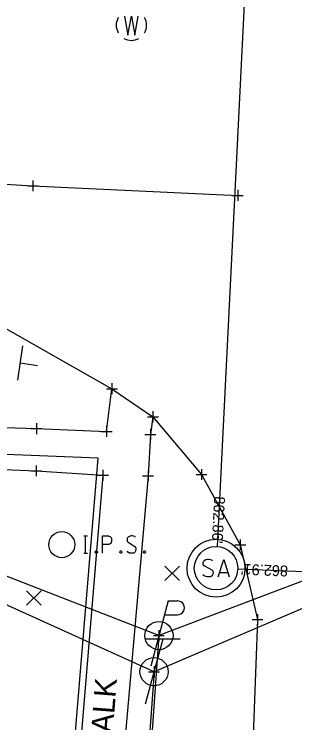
# Model space of a CAD drawing. Extents: x 1380550 to 1381945, y 468927 to 470496.
# Drawn here: x 1381582.5 to 1381608.3, y 470212.8 to 470278.1 of the extents above; entities that cross this region are included whole.
import ezdxf

# ---------------------------------------------------------------- set-up
doc = ezdxf.new("R2010")
doc.units = 0
for name, color, linetype in [('DR_X_Storm_Sewer', 7, 'Continuous'), ('DR_X_Text', 7, 'Continuous'), ('GK_Drainage_Nodes', 7, 'Continuous'), ('PV_X_COP', 7, 'Continuous'), ('PV_X_EOP', 7, 'Continuous'), ('PV_X_Walk', 7, 'Continuous'), ('RD_X_Text', 7, 'Continuous'), ('RW_X_Esmt_General', 7, 'Continuous'), ('SC_Scratch1', 7, 'Continuous'), ('SN_X_Public', 7, 'Continuous'), ('SV_P_Mon_Cells_Set', 7, 'Continuous'), ('SV_X_Random_Point', 7, 'Continuous'), ('SV_X_Shot_Marker', 7, 'Continuous'), ('UT_X_Electric', 7, 'Continuous'), ('UT_X_Electric_Cells', 7, 'Continuous'), ('UT_X_Sanitary_Cells', 7, 'Continuous'), ('UT_X_Sanitary_Line', 7, 'Continuous'), ('UT_X_Telecom', 7, 'Continuous'), ('UT_X_Telecom_Cells', 7, 'Continuous'), ('UT_X_Water_Cells', 7, 'Continuous')]:
    doc.layers.add(name, color=color, linetype=linetype)

msp = doc.modelspace()

# ---------------------------------------------------------------- linework, layer by layer
at = {"layer": 'DR_X_Storm_Sewer'}
msp.add_line((1381906.161, 470214.727), (1381603.055, 470226.96), dxfattribs=at)
at = {"layer": 'GK_Drainage_Nodes'}
for p, q in [((1381601.057, 470229.041), (1381601.057, 470229.041)), ((1381601.057, 470227.041), (1381601.057, 470227.041)), ((1381601.057, 470227.041), (1381601.057, 470227.041)), ((1381601.057, 470227.041), (1381601.057, 470227.041)), ((1381601.057, 470225.041), (1381601.057, 470225.041))]:
    msp.add_line(p, q, dxfattribs=at)
msp.add_circle((1381601.057, 470227.041), 2, dxfattribs=at)
at = {"layer": 'PV_X_COP'}
msp.add_lwpolyline([(1381547.543, 470264.484), (1381567.85, 470263.258), (1381584.182, 470262.283), (1381603.07, 470261.395)], dxfattribs=at)
at = {"layer": 'PV_X_EOP'}
msp.add_lwpolyline([(1381575.388, 470244.04), (1381576.993, 470244.172), (1381579.545, 470245.54), (1381580.634, 470247.96), (1381580.965, 470249.541), (1381591.472, 470243.585), (1381595.246, 470241.001), (1381599.724, 470235.672), (1381603.295, 470229.192), (1381604.877, 470222.306), (1381604.1, 470201.731), (1381602.36, 470179.429), (1381598.627, 470125.511), (1381593.594, 470071.886), (1381589.534, 470020.646), (1381585.494, 469971.089), (1381582.039, 469928.84), (1381578.382, 469880.278), (1381576.859, 469862.024), (1381576.832, 469860.709), (1381576.155, 469857.385), (1381571.588, 469847.123), (1381563.138, 469838.251)], dxfattribs=at)
at = {"layer": 'PV_X_Walk'}
for points in [[(1381542.819, 470241.667), (1381568.313, 470240.569), (1381578.584, 470240.095), (1381584.519, 470239.902), (1381590.984, 470239.649), (1381591.472, 470243.585)], [(1381595.246, 470241.001), (1381595.008, 470239.378), (1381594.794, 470235.558), (1381591.944, 470203.127), (1381590.146, 470180.146), (1381585.845, 470126.107), (1381581.453, 470072.835), (1381577.219, 470021.474), (1381573.16, 469971.68), (1381569.701, 469929.431), (1381565.599, 469880.892), (1381564.412, 469866.997), (1381562.952, 469848.389), (1381561.899, 469840.883)], [(1381542.564, 470237.64), (1381568.337, 470236.695), (1381578.506, 470236.262), (1381584.487, 470236.02), (1381590.642, 470235.62), (1381587.955, 470203.415), (1381586.625, 470180.461), (1381581.932, 470126.464), (1381577.652, 470073.239), (1381573.197, 470021.541), (1381569.148, 469971.738), (1381565.643, 469929.65), (1381561.644, 469881.156), (1381560.457, 469867.318), (1381559.272, 469848.708), (1381558.347, 469840.136)]]:
    msp.add_lwpolyline(points, dxfattribs=at)
at = {"layer": 'RW_X_Esmt_General'}
msp.add_lwpolyline([(1381490.401, 469029.464), (1381590.199, 470237.184), (1380558.689, 470277.035)], dxfattribs=at)
at = {"layer": 'SN_X_Public'}
for p, q in [((1381582.814, 470244.371), (1381583.252, 470247.541)), ((1381583.033, 470245.956), (1381584.618, 470245.737))]:
    msp.add_line(p, q, dxfattribs=at)
at = {"layer": 'SV_P_Mon_Cells_Set'}
for points in [[(1381588.87, 470230.016), (1381589.223, 470230.016)], [(1381589.046, 470228.416), (1381589.046, 470230.016)], [(1381590.612, 470228.416), (1381590.612, 470230.016), (1381591.141, 470230.016), (1381591.196, 470230.003), (1381591.273, 470229.978), (1381591.306, 470229.953), (1381591.339, 470229.928), (1381591.383, 470229.865), (1381591.416, 470229.802), (1381591.438, 470229.701), (1381591.438, 470229.55), (1381591.427, 470229.499), (1381591.405, 470229.424), (1381591.361, 470229.336), (1381591.317, 470229.298), (1381591.284, 470229.273), (1381591.229, 470229.247), (1381591.141, 470229.235), (1381590.612, 470229.235)], [(1381593.621, 470229.902), (1381593.599, 470229.928), (1381593.566, 470229.953), (1381593.467, 470229.991), (1381593.345, 470230.016), (1381593.257, 470230.016), (1381593.224, 470230.016), (1381593.081, 470229.978), (1381592.96, 470229.902), (1381592.882, 470229.802), (1381592.86, 470229.701), (1381592.86, 470229.625), (1381592.882, 470229.524), (1381592.971, 470229.436), (1381593.577, 470229.058), (1381593.632, 470229.008), (1381593.654, 470228.958), (1381593.676, 470228.882), (1381593.676, 470228.806), (1381593.665, 470228.731), (1381593.654, 470228.681), (1381593.632, 470228.617), (1381593.61, 470228.567), (1381593.588, 470228.529), (1381593.555, 470228.491), (1381593.522, 470228.466), (1381593.478, 470228.441), (1381593.445, 470228.429), (1381593.345, 470228.416), (1381593.191, 470228.416), (1381593.092, 470228.441), (1381592.948, 470228.529), (1381592.86, 470228.605)], [(1381590.005, 470228.63), (1381590.06, 470228.63), (1381590.094, 470228.605), (1381590.127, 470228.555), (1381590.127, 470228.491), (1381590.094, 470228.441), (1381590.06, 470228.416), (1381590.005, 470228.416), (1381589.972, 470228.441), (1381589.939, 470228.491), (1381589.939, 470228.555), (1381589.972, 470228.605), (1381590.005, 470228.63)], [(1381592.254, 470228.63), (1381592.309, 470228.63), (1381592.342, 470228.605), (1381592.375, 470228.555), (1381592.375, 470228.491), (1381592.342, 470228.441), (1381592.309, 470228.416), (1381592.254, 470228.416), (1381592.221, 470228.441), (1381592.188, 470228.491), (1381592.188, 470228.555), (1381592.221, 470228.605), (1381592.254, 470228.63)], [(1381594.437, 470228.63), (1381594.492, 470228.63), (1381594.525, 470228.605), (1381594.558, 470228.555), (1381594.558, 470228.491), (1381594.525, 470228.441), (1381594.492, 470228.416), (1381594.437, 470228.416), (1381594.403, 470228.441), (1381594.371, 470228.491), (1381594.371, 470228.555), (1381594.403, 470228.605), (1381594.437, 470228.63)], [(1381588.87, 470228.416), (1381589.223, 470228.416)]]:
    msp.add_lwpolyline(points, dxfattribs=at)
msp.add_circle((1381586.851, 470229.214), 1.2, dxfattribs=at)
at = {"layer": 'SV_X_Random_Point'}
for p, q in [((1381596.356, 470225.899), (1381597.69, 470227.234)), ((1381596.356, 470227.234), (1381597.69, 470225.899)), ((1381583.61, 470223.635), (1381584.944, 470224.97)), ((1381583.61, 470224.97), (1381584.944, 470223.635))]:
    msp.add_line(p, q, dxfattribs=at)
at = {"layer": 'SV_X_Shot_Marker'}
for p, q in [((1381584.182, 470262.783), (1381584.182, 470261.783)), ((1381583.682, 470262.283), (1381584.682, 470262.283)), ((1381584.182, 470262.283), (1381584.182, 470262.283)), ((1381603.07, 470261.895), (1381603.07, 470260.895)), ((1381602.57, 470261.395), (1381603.57, 470261.395)), ((1381603.07, 470261.395), (1381603.07, 470261.395)), ((1381590.972, 470243.585), (1381591.972, 470243.585)), ((1381590.972, 470243.585), (1381591.972, 470243.585)), ((1381591.472, 470244.085), (1381591.472, 470243.085)), ((1381591.472, 470244.085), (1381591.472, 470243.085)), ((1381591.472, 470243.585), (1381591.472, 470243.585)), ((1381591.472, 470243.585), (1381591.472, 470243.585)), ((1381594.746, 470241.001), (1381595.746, 470241.001)), ((1381594.746, 470241.001), (1381595.746, 470241.001)), ((1381594.746, 470241.001), (1381595.746, 470241.001)), ((1381595.246, 470241.501), (1381595.246, 470240.501)), ((1381595.246, 470241.501), (1381595.246, 470240.501)), ((1381595.246, 470241.501), (1381595.246, 470240.501)), ((1381595.246, 470241.001), (1381595.246, 470241.001)), ((1381595.246, 470241.001), (1381595.246, 470241.001)), ((1381595.246, 470241.001), (1381595.246, 470241.001)), ((1381584.519, 470240.402), (1381584.519, 470239.402)), ((1381584.019, 470239.902), (1381585.019, 470239.902)), ((1381584.519, 470239.902), (1381584.519, 470239.902)), ((1381590.484, 470239.649), (1381591.484, 470239.649)), ((1381590.984, 470240.149), (1381590.984, 470239.149)), ((1381590.984, 470239.649), (1381590.984, 470239.649)), ((1381595.008, 470239.878), (1381595.008, 470238.878)), ((1381594.508, 470239.378), (1381595.508, 470239.378)), ((1381595.008, 470239.378), (1381595.008, 470239.378)), ((1381584.487, 470236.52), (1381584.487, 470235.52)), ((1381583.987, 470236.02), (1381584.987, 470236.02)), ((1381584.487, 470236.02), (1381584.487, 470236.02)), ((1381590.642, 470236.12), (1381590.642, 470235.12)), ((1381594.794, 470236.058), (1381594.794, 470235.058)), ((1381599.224, 470235.672), (1381600.224, 470235.672)), ((1381599.724, 470236.172), (1381599.724, 470235.172)), ((1381599.724, 470235.672), (1381599.724, 470235.672)), ((1381590.142, 470235.62), (1381591.142, 470235.62)), ((1381590.642, 470235.62), (1381590.642, 470235.62)), ((1381594.294, 470235.558), (1381595.294, 470235.558)), ((1381594.794, 470235.558), (1381594.794, 470235.558)), ((1381602.795, 470229.192), (1381603.795, 470229.192)), ((1381603.295, 470229.692), (1381603.295, 470228.692)), ((1381603.295, 470229.192), (1381603.295, 470229.192)), ((1381604.877, 470222.806), (1381604.877, 470221.806)), ((1381604.377, 470222.306), (1381605.377, 470222.306)), ((1381604.877, 470222.306), (1381604.877, 470222.306)), ((1381595.795, 470221.333), (1381595.795, 470220.333)), ((1381595.795, 470221.333), (1381595.795, 470220.333)), ((1381595.295, 470220.833), (1381596.295, 470220.833)), ((1381595.295, 470220.833), (1381596.295, 470220.833)), ((1381595.795, 470220.833), (1381595.795, 470220.833)), ((1381595.795, 470220.833), (1381595.795, 470220.833)), ((1381595.346, 470218.01), (1381595.346, 470217.01)), ((1381595.346, 470218.01), (1381595.346, 470217.01)), ((1381594.846, 470217.51), (1381595.846, 470217.51)), ((1381594.846, 470217.51), (1381595.846, 470217.51)), ((1381595.346, 470217.51), (1381595.346, 470217.51)), ((1381595.346, 470217.51), (1381595.346, 470217.51))]:
    msp.add_line(p, q, dxfattribs=at)
at = {"layer": 'UT_X_Electric'}
for points in [[(1381665.562, 470247.404), (1381595.795, 470220.833), (1381581.264, 470018.199), (1381571.968, 469887.64), (1381559.775, 469757.408), (1381543.86, 469565.781), (1381529.165, 469390.12), (1381515.279, 469203.101), (1381540.8, 469054.263)], [(1381595.795, 470220.833), (1381540.532, 470242.354)]]:
    msp.add_lwpolyline(points, dxfattribs=at)
at = {"layer": 'UT_X_Electric_Cells'}
for p, q in [((1381596.652, 470224.033), (1381595.045, 470218.033)), ((1381596.652, 470224.033), (1381597.502, 470224.033)), ((1381596.31, 470222.758), (1381597.502, 470222.758))]:
    msp.add_line(p, q, dxfattribs=at)
msp.add_circle((1381595.795, 470220.833), 1.3, dxfattribs=at)
msp.add_arc((1381597.514, 470223.396), 0.638, 268.8767, 91.1233, dxfattribs=at)
at = {"layer": 'UT_X_Sanitary_Cells'}
for points in [[(1381600.724, 470227.727), (1381600.699, 470227.753), (1381600.661, 470227.778), (1381600.548, 470227.816), (1381600.409, 470227.841), (1381600.309, 470227.841), (1381600.271, 470227.841), (1381600.107, 470227.803), (1381599.969, 470227.727), (1381599.88, 470227.627), (1381599.855, 470227.526), (1381599.855, 470227.45), (1381599.88, 470227.349), (1381599.981, 470227.261), (1381600.674, 470226.883), (1381600.737, 470226.833), (1381600.762, 470226.783), (1381600.787, 470226.707), (1381600.787, 470226.631), (1381600.775, 470226.556), (1381600.762, 470226.505), (1381600.737, 470226.442), (1381600.712, 470226.392), (1381600.687, 470226.354), (1381600.649, 470226.316), (1381600.611, 470226.291), (1381600.561, 470226.266), (1381600.523, 470226.253), (1381600.409, 470226.241), (1381600.233, 470226.241), (1381600.12, 470226.266), (1381599.956, 470226.354), (1381599.855, 470226.43)], [(1381601.266, 470226.241), (1381601.77, 470227.841), (1381602.261, 470226.241)], [(1381602.135, 470226.619), (1381601.392, 470226.619)]]:
    msp.add_lwpolyline(points, dxfattribs=at)
for radius in [2.667, 2]:
    msp.add_circle((1381601.057, 470227.041), radius, dxfattribs=at)
at = {"layer": 'UT_X_Sanitary_Line'}
msp.add_line((1381607.902, 470363.885), (1381601.157, 470229.038), dxfattribs=at)
at = {"layer": 'UT_X_Telecom'}
for points in [[(1381665.562, 470247.404), (1381595.346, 470217.51), (1381581.264, 470018.199), (1381571.968, 469887.64), (1381559.775, 469757.408), (1381543.86, 469565.781), (1381529.165, 469390.12), (1381515.279, 469203.101), (1381540.8, 469054.263)], [(1381595.346, 470217.51), (1381540.532, 470242.354)]]:
    msp.add_lwpolyline(points, dxfattribs=at)
at = {"layer": 'UT_X_Telecom_Cells'}
for p, q in [((1381596.149, 470220.51), (1381594.543, 470214.51)), ((1381597.749, 470220.51), (1381594.549, 470220.51))]:
    msp.add_line(p, q, dxfattribs=at)
msp.add_circle((1381595.346, 470217.51), 1.3, dxfattribs=at)
at = {"layer": 'UT_X_Water_Cells'}
msp.add_line((1381593.263, 470277.078), (1381593.263, 470277.078), dxfattribs=at)
msp.add_lwpolyline([(1381592.626, 470277.898), (1381592.945, 470276.174), (1381593.263, 470277.898), (1381593.583, 470276.174), (1381593.9, 470277.898)], dxfattribs=at)
for start, end in [(150.01836, 209.98164), (330.01836, 29.98164), (239.98426, 299.98164)]:
    msp.add_arc((1381593.263, 470277.079), 1.4, start, end, dxfattribs=at)

# ---------------------------------------------------------------- texts
at = {"layer": 'DR_X_Text'}
msp.add_text('APPROX. DIR.', height=2.8, rotation=19.95844, dxfattribs=at).set_placement((1381575.732, 470276.697))
at = {"layer": 'RD_X_Text'}
msp.add_text('SIDEWALK', height=2, rotation=85.52099, dxfattribs=at).set_placement((1381590.858, 470203.069))
at = {"layer": 'SC_Scratch1'}
for s, rotation, p in [("862.86'", 267.1364, (1381600.889, 470233.69)), ("862.91'", 177.68886, (1381607.704, 470227.273))]:
    msp.add_text(s, height=1, rotation=rotation, dxfattribs=at).set_placement(p)

doc.saveas('drawing.dxf')
